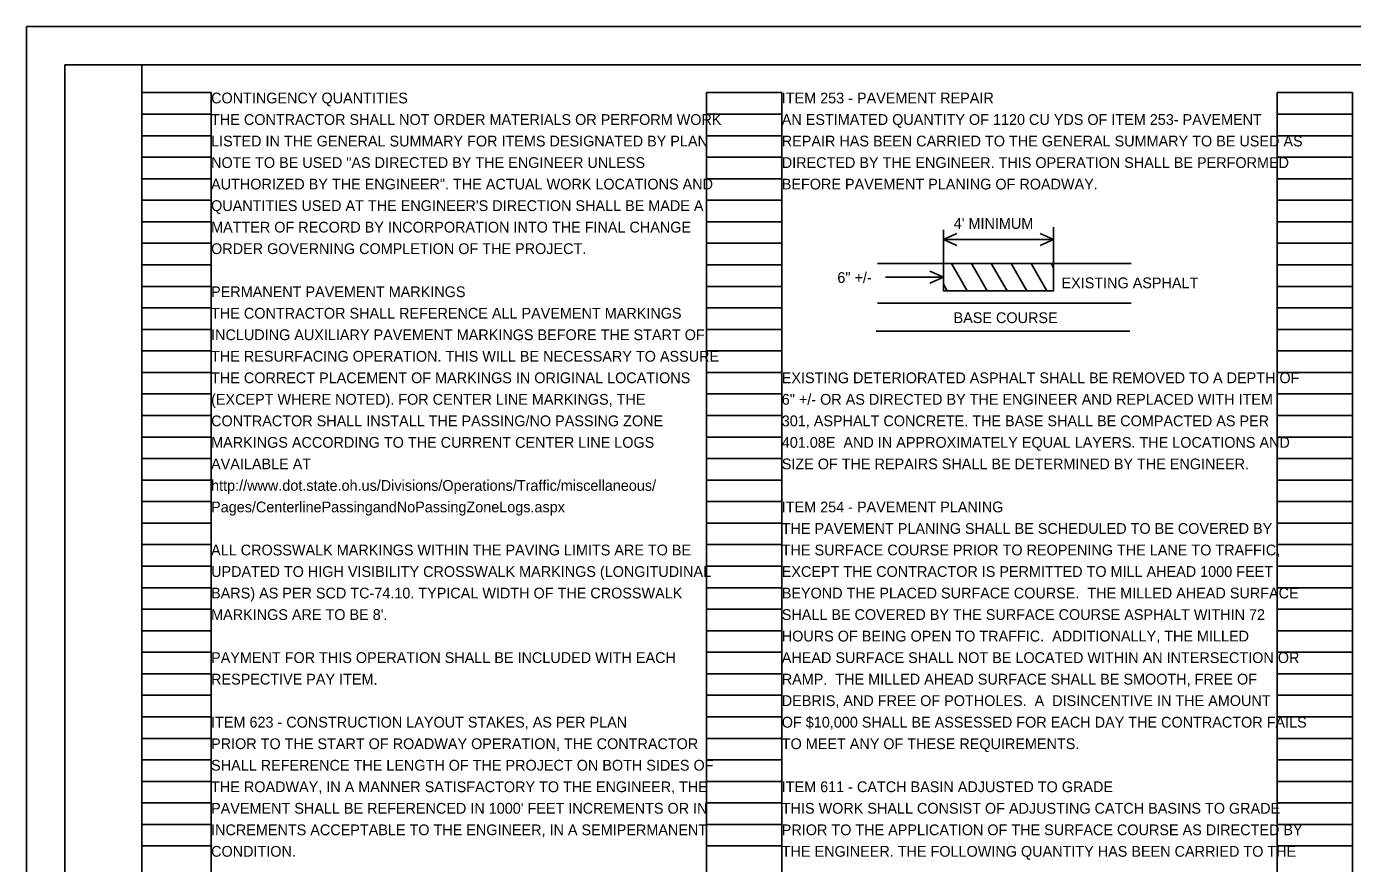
# Model space of a CAD drawing. Extents: x 31.7 to 83.9, y -7.4 to 14.6.
# Drawn here: x 49.93 to 67.17, y 3.72 to 14.61 of the extents above; entities that cross this region are included whole.
import ezdxf

# ---------------------------------------------------------------- set-up
doc = ezdxf.new("R2010")
doc.units = 0
for name, color, linetype in [('Default', 7, 'Continuous'), ('SH_Border', 7, 'Continuous'), ('SH_Cut_Line', 7, 'Continuous'), ('SH_Data', 7, 'Continuous'), ('SH_Text', 7, 'Continuous')]:
    doc.layers.add(name, color=color, linetype=linetype)

msp = doc.modelspace()

# ---------------------------------------------------------------- linework, layer by layer
at = {"layer": 'Default'}
for p, q in [((61.848, 11.967), (61.848, 11.169)), ((61.848, 11.84), (62.022, 11.918)), ((63.105, 11.918), (63.279, 11.84)), ((63.279, 11.998), (63.279, 11.169)), ((61.848, 11.84), (63.279, 11.84)), ((61.848, 11.84), (62.022, 11.763)), ((63.105, 11.763), (63.279, 11.84)), ((60.989, 11.529), (64.287, 11.529)), ((61.673, 11.427), (61.847, 11.349)), ((62.157, 11.171), (61.953, 11.529)), ((62.416, 11.171), (62.212, 11.529)), ((62.675, 11.171), (62.47, 11.529)), ((62.934, 11.171), (62.73, 11.529)), ((63.194, 11.171), (62.99, 11.529)), ((63.279, 11.475), (63.248, 11.529)), ((61.096, 11.349), (61.847, 11.349)), ((61.673, 11.271), (61.847, 11.349)), ((61.898, 11.171), (61.848, 11.259)), ((60.989, 11.013), (64.287, 11.013)), ((60.972, 10.646), (64.27, 10.646))]:
    msp.add_line(p, q, dxfattribs=at)
at = {"layer": 'SH_Border'}
for points in [[(50.426, 14.11), (51.426, 14.11), (51.426, -6.89), (50.426, -6.89)], [(51.426, 14.11), (83.426, 14.11), (83.426, -6.89), (51.426, -6.89)]]:
    msp.add_lwpolyline(points, close=True, dxfattribs=at)
at = {"layer": 'SH_Cut_Line'}
msp.add_lwpolyline([(49.926, -7.39), (83.926, -7.39), (83.926, 14.61), (49.926, 14.61)], close=True, dxfattribs=at)
at = {"layer": 'SH_Data'}
for p, q in [((51.426, -6.41), (51.426, 13.75)), ((51.426, 13.75), (52.326, 13.75)), ((52.326, -6.41), (52.326, 13.75)), ((58.766, -6.41), (58.766, 13.75)), ((58.766, 13.75), (59.746, 13.75)), ((59.746, -6.41), (59.746, 13.75)), ((66.186, -6.41), (66.186, 13.75)), ((66.186, 13.75), (67.166, 13.75)), ((67.166, -6.41), (67.166, 13.75)), ((51.426, 13.47), (52.326, 13.47)), ((58.766, 13.47), (59.746, 13.47)), ((66.186, 13.47), (67.166, 13.47)), ((51.426, 13.19), (52.326, 13.19)), ((58.766, 13.19), (59.746, 13.19)), ((66.186, 13.19), (67.166, 13.19)), ((51.426, 12.91), (52.326, 12.91)), ((58.766, 12.91), (59.746, 12.91)), ((66.186, 12.91), (67.166, 12.91)), ((51.426, 12.63), (52.326, 12.63)), ((58.766, 12.63), (59.746, 12.63)), ((66.186, 12.63), (67.166, 12.63)), ((51.426, 12.35), (52.326, 12.35)), ((58.766, 12.35), (59.746, 12.35)), ((66.186, 12.35), (67.166, 12.35)), ((51.426, 12.07), (52.326, 12.07)), ((58.766, 12.07), (59.746, 12.07)), ((66.186, 12.07), (67.166, 12.07)), ((51.426, 11.79), (52.326, 11.79)), ((58.766, 11.79), (59.746, 11.79)), ((66.186, 11.79), (67.166, 11.79)), ((51.426, 11.51), (52.326, 11.51)), ((58.766, 11.51), (59.746, 11.51)), ((66.186, 11.51), (67.166, 11.51)), ((51.426, 11.23), (52.326, 11.23)), ((58.766, 11.23), (59.746, 11.23)), ((66.186, 11.23), (67.166, 11.23)), ((51.426, 10.95), (52.326, 10.95)), ((58.766, 10.95), (59.746, 10.95)), ((66.186, 10.95), (67.166, 10.95)), ((51.426, 10.67), (52.326, 10.67)), ((58.766, 10.67), (59.746, 10.67)), ((66.186, 10.67), (67.166, 10.67)), ((51.426, 10.39), (52.326, 10.39)), ((58.766, 10.39), (59.746, 10.39)), ((66.186, 10.39), (67.166, 10.39)), ((51.426, 10.11), (52.326, 10.11)), ((58.766, 10.11), (59.746, 10.11)), ((66.186, 10.11), (67.166, 10.11)), ((51.426, 9.83), (52.326, 9.83)), ((58.766, 9.83), (59.746, 9.83)), ((66.186, 9.83), (67.166, 9.83)), ((51.426, 9.55), (52.326, 9.55)), ((58.766, 9.55), (59.746, 9.55)), ((66.186, 9.55), (67.166, 9.55)), ((51.426, 9.27), (52.326, 9.27)), ((58.766, 9.27), (59.746, 9.27)), ((66.186, 9.27), (67.166, 9.27)), ((51.426, 8.99), (52.326, 8.99)), ((58.766, 8.99), (59.746, 8.99)), ((66.186, 8.99), (67.166, 8.99)), ((51.426, 8.71), (52.326, 8.71)), ((58.766, 8.71), (59.746, 8.71)), ((66.186, 8.71), (67.166, 8.71)), ((51.426, 8.43), (52.326, 8.43)), ((58.766, 8.43), (59.746, 8.43)), ((66.186, 8.43), (67.166, 8.43)), ((51.426, 8.15), (52.326, 8.15)), ((58.766, 8.15), (59.746, 8.15)), ((66.186, 8.15), (67.166, 8.15)), ((51.426, 7.87), (52.326, 7.87)), ((58.766, 7.87), (59.746, 7.87)), ((66.186, 7.87), (67.166, 7.87)), ((51.426, 7.59), (52.326, 7.59)), ((58.766, 7.59), (59.746, 7.59)), ((66.186, 7.59), (67.166, 7.59)), ((51.426, 7.31), (52.326, 7.31)), ((58.766, 7.31), (59.746, 7.31)), ((66.186, 7.31), (67.166, 7.31)), ((51.426, 7.03), (52.326, 7.03)), ((58.766, 7.03), (59.746, 7.03)), ((66.186, 7.03), (67.166, 7.03)), ((51.426, 6.75), (52.326, 6.75)), ((58.766, 6.75), (59.746, 6.75)), ((66.186, 6.75), (67.166, 6.75)), ((51.426, 6.47), (52.326, 6.47)), ((58.766, 6.47), (59.746, 6.47)), ((66.186, 6.47), (67.166, 6.47)), ((51.426, 6.19), (52.326, 6.19)), ((58.766, 6.19), (59.746, 6.19)), ((66.186, 6.19), (67.166, 6.19)), ((51.426, 5.91), (52.326, 5.91)), ((58.766, 5.91), (59.746, 5.91)), ((66.186, 5.91), (67.166, 5.91)), ((51.426, 5.63), (52.326, 5.63)), ((58.766, 5.63), (59.746, 5.63)), ((66.186, 5.63), (67.166, 5.63)), ((51.426, 5.35), (52.326, 5.35)), ((58.766, 5.35), (59.746, 5.35)), ((66.186, 5.35), (67.166, 5.35)), ((51.426, 5.07), (52.326, 5.07)), ((58.766, 5.07), (59.746, 5.07)), ((66.186, 5.07), (67.166, 5.07)), ((51.426, 4.79), (52.326, 4.79)), ((58.766, 4.79), (59.746, 4.79)), ((66.186, 4.79), (67.166, 4.79)), ((51.426, 4.51), (52.326, 4.51)), ((58.766, 4.51), (59.746, 4.51)), ((66.186, 4.51), (67.166, 4.51)), ((51.426, 4.23), (52.326, 4.23)), ((58.766, 4.23), (59.746, 4.23)), ((66.186, 4.23), (67.166, 4.23)), ((51.426, 3.95), (52.326, 3.95)), ((58.766, 3.95), (59.746, 3.95)), ((66.186, 3.95), (67.166, 3.95))]:
    msp.add_line(p, q, dxfattribs=at)
at = {"layer": 'SH_Text'}
msp.add_lwpolyline([(61.848, 11.171), (61.848, 11.171), (63.279, 11.171)], dxfattribs=at)

# ---------------------------------------------------------------- texts
at = {"layer": 'Default'}
for s, p in [("4' MINIMUM", (61.982, 11.978)), ('6" +/- ', (60.469, 11.275)), ('EXISTING ASPHALT', (63.383, 11.205)), ('BASE COURSE', (61.98, 10.752))]:
    msp.add_text(s, height=0.14, dxfattribs=at).set_placement(p)
at = {"layer": 'SH_Text'}
for s, p in [('CONTINGENCY QUANTITIES', (52.326, 13.61)), ('ITEM 253 - PAVEMENT REPAIR', (59.746, 13.61)), ('THE CONTRACTOR SHALL NOT ORDER MATERIALS OR PERFORM WORK ', (52.326, 13.33)), ('AN ESTIMATED QUANTITY OF 1120 CU YDS OF ITEM 253- PAVEMENT ', (59.746, 13.33)), ('LISTED IN THE GENERAL SUMMARY FOR ITEMS DESIGNATED BY PLAN ', (52.326, 13.05)), ('REPAIR HAS BEEN CARRIED TO THE GENERAL SUMMARY TO BE USED AS ', (59.746, 13.05)), ('NOTE TO BE USED "AS DIRECTED BY THE ENGINEER UNLESS ', (52.326, 12.77)), ('DIRECTED BY THE ENGINEER. THIS OPERATION SHALL BE PERFORMED ', (59.746, 12.77)), ('AUTHORIZED BY THE ENGINEER". THE ACTUAL WORK LOCATIONS AND ', (52.326, 12.49)), ('BEFORE PAVEMENT PLANING OF ROADWAY.', (59.746, 12.49)), ("QUANTITIES USED AT THE ENGINEER'S DIRECTION SHALL BE MADE A ", (52.326, 12.21)), ('MATTER OF RECORD BY INCORPORATION INTO THE FINAL CHANGE ', (52.326, 11.93)), ('ORDER GOVERNING COMPLETION OF THE PROJECT.', (52.326, 11.65)), ('PERMANENT PAVEMENT MARKINGS', (52.326, 11.09)), ('THE CONTRACTOR SHALL REFERENCE ALL PAVEMENT MARKINGS ', (52.326, 10.81)), ('INCLUDING AUXILIARY PAVEMENT MARKINGS BEFORE THE START OF ', (52.326, 10.53)), ('THE RESURFACING OPERATION. THIS WILL BE NECESSARY TO ASSURE ', (52.326, 10.25)), ('THE CORRECT PLACEMENT OF MARKINGS IN ORIGINAL LOCATIONS ', (52.326, 9.97)), ('EXISTING DETERIORATED ASPHALT SHALL BE REMOVED TO A DEPTH OF ', (59.746, 9.97)), ('(EXCEPT WHERE NOTED). FOR CENTER LINE MARKINGS, THE ', (52.326, 9.69)), ('6" +/- OR AS DIRECTED BY THE ENGINEER AND REPLACED WITH ITEM ', (59.746, 9.69)), ('CONTRACTOR SHALL INSTALL THE PASSING/NO PASSING ZONE ', (52.326, 9.41)), ('301, ASPHALT CONCRETE. THE BASE SHALL BE COMPACTED AS PER ', (59.746, 9.41)), ('MARKINGS ACCORDING TO THE CURRENT CENTER LINE LOGS ', (52.326, 9.13)), ('401.08E  AND IN APPROXIMATELY EQUAL LAYERS. THE LOCATIONS AND ', (59.746, 9.13)), ('AVAILABLE AT', (52.326, 8.85)), ('SIZE OF THE REPAIRS SHALL BE DETERMINED BY THE ENGINEER.', (59.746, 8.85)), ('http://www.dot.state.oh.us/Divisions/Operations/Traffic/miscellaneous/', (52.326, 8.57)), ('Pages/CenterlinePassingandNoPassingZoneLogs.aspx', (52.326, 8.29)), ('ITEM 254 - PAVEMENT PLANING', (59.746, 8.29)), ('THE PAVEMENT PLANING SHALL BE SCHEDULED TO BE COVERED BY ', (59.746, 8.01)), ('ALL CROSSWALK MARKINGS WITHIN THE PAVING LIMITS ARE TO BE ', (52.326, 7.73)), ('THE SURFACE COURSE PRIOR TO REOPENING THE LANE TO TRAFFIC, ', (59.746, 7.73)), ('UPDATED TO HIGH VISIBILITY CROSSWALK MARKINGS (LONGITUDINAL ', (52.326, 7.45)), ('EXCEPT THE CONTRACTOR IS PERMITTED TO MILL AHEAD 1000 FEET ', (59.746, 7.45)), ('BARS) AS PER SCD TC-74.10. TYPICAL WIDTH OF THE CROSSWALK ', (52.326, 7.17)), ('BEYOND THE PLACED SURFACE COURSE.  THE MILLED AHEAD SURFACE ', (59.746, 7.17)), ("MARKINGS ARE TO BE 8'.", (52.326, 6.89)), ('SHALL BE COVERED BY THE SURFACE COURSE ASPHALT WITHIN 72 ', (59.746, 6.89)), ('HOURS OF BEING OPEN TO TRAFFIC.  ADDITIONALLY, THE MILLED ', (59.746, 6.61)), ('PAYMENT FOR THIS OPERATION SHALL BE INCLUDED WITH EACH ', (52.326, 6.33)), ('AHEAD SURFACE SHALL NOT BE LOCATED WITHIN AN INTERSECTION OR ', (59.746, 6.33)), ('RESPECTIVE PAY ITEM.', (52.326, 6.05)), ('RAMP.  THE MILLED AHEAD SURFACE SHALL BE SMOOTH, FREE OF ', (59.746, 6.05)), ('DEBRIS, AND FREE OF POTHOLES.  A  DISINCENTIVE IN THE AMOUNT ', (59.746, 5.77)), ('ITEM 623 - CONSTRUCTION LAYOUT STAKES, AS PER PLAN', (52.326, 5.49)), ('OF $10,000 SHALL BE ASSESSED FOR EACH DAY THE CONTRACTOR FAILS ', (59.746, 5.49)), ('PRIOR TO THE START OF ROADWAY OPERATION, THE CONTRACTOR ', (52.326, 5.21)), ('TO MEET ANY OF THESE REQUIREMENTS.', (59.746, 5.21)), ('SHALL REFERENCE THE LENGTH OF THE PROJECT ON BOTH SIDES OF ', (52.326, 4.93)), ('THE ROADWAY, IN A MANNER SATISFACTORY TO THE ENGINEER, THE ', (52.326, 4.65)), ('ITEM 611 - CATCH BASIN ADJUSTED TO GRADE', (59.746, 4.65)), ("PAVEMENT SHALL BE REFERENCED IN 1000' FEET INCREMENTS OR IN ", (52.326, 4.37)), ('THIS WORK SHALL CONSIST OF ADJUSTING CATCH BASINS TO GRADE ', (59.746, 4.37)), ('INCREMENTS ACCEPTABLE TO THE ENGINEER, IN A SEMIPERMANENT ', (52.326, 4.09)), ('PRIOR TO THE APPLICATION OF THE SURFACE COURSE AS DIRECTED BY ', (59.746, 4.09)), ('CONDITION.', (52.326, 3.81)), ('THE ENGINEER. THE FOLLOWING QUANTITY HAS BEEN CARRIED TO THE ', (59.746, 3.81))]:
    msp.add_text(s, height=0.14, dxfattribs=at).set_placement(p)

doc.saveas('drawing.dxf')
